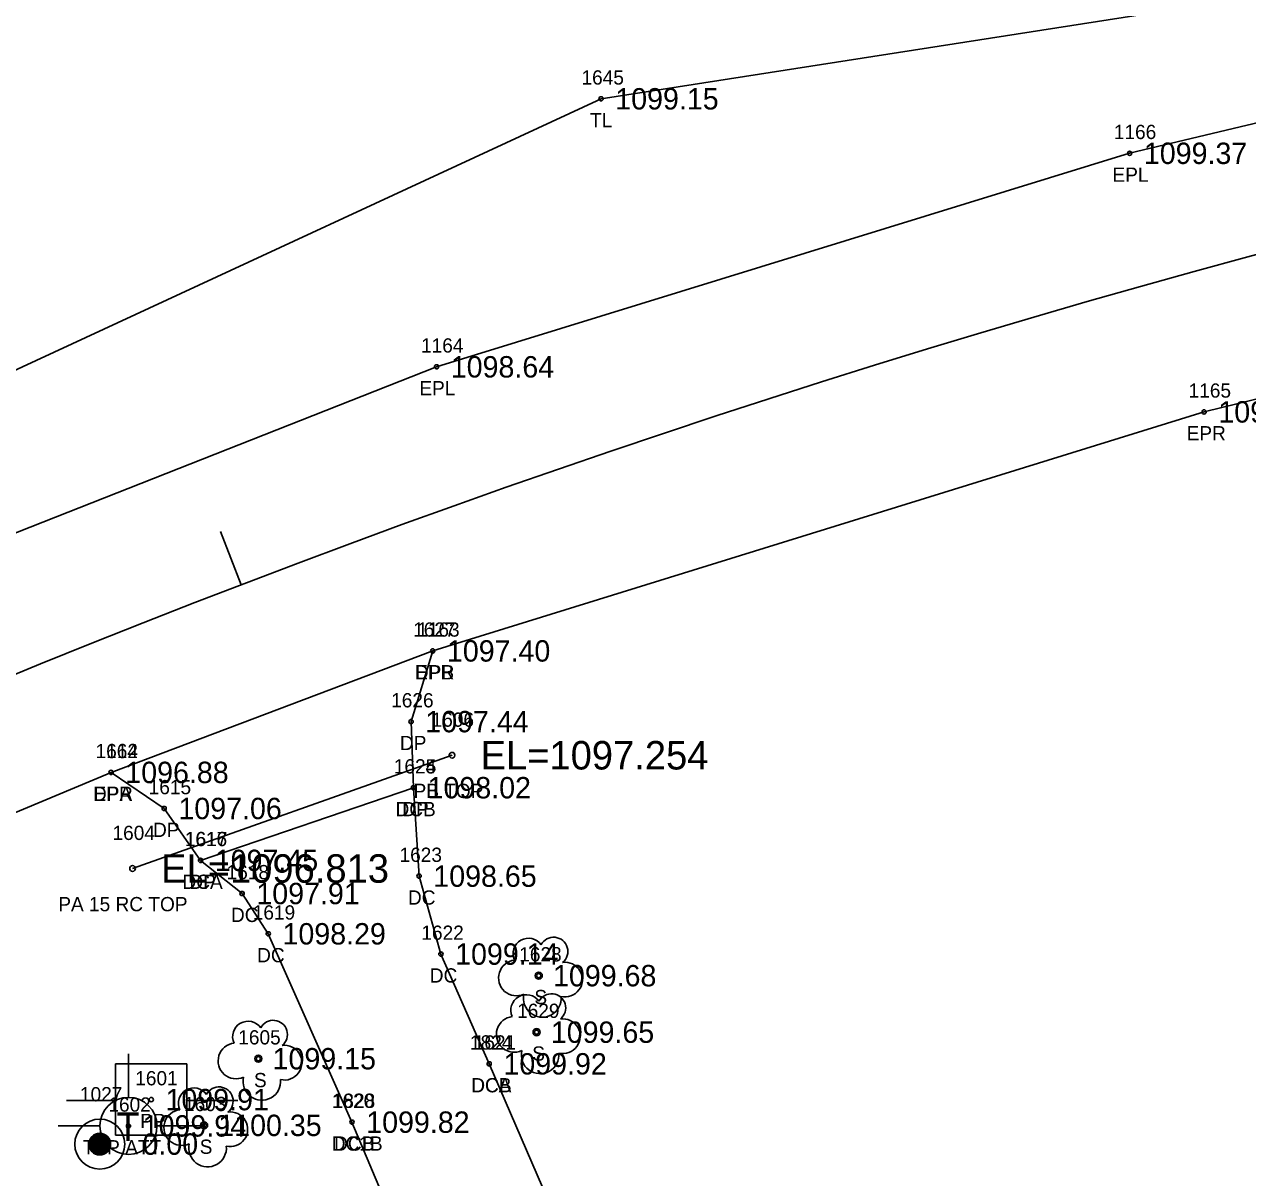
# Model space of a CAD drawing. Extents: x 1539151 to 1541799, y 1198646 to 1201165.
# Drawn here: x 1541070.5 to 1541156.3, y 1200343.1 to 1200424.1 of the extents above; entities that cross this region are included whole.
import ezdxf

# ---------------------------------------------------------------- set-up
doc = ezdxf.new("R2010")
doc.units = 0
for name, color, linetype in [('RD_EX_Conc', 7, 'Continuous'), ('RD_EX_Conc_txCode', 7, 'Continuous'), ('RD_EX_DR_Pipe', 7, 'Continuous'), ('RD_EX_DR_Pipe_txCode', 7, 'Continuous'), ('RD_EX_Driveway', 7, 'Continuous'), ('RD_EX_Driveway_txCode', 7, 'Continuous'), ('RD_EX_DV_Prop_txCode', 7, 'Continuous'), ('RD_EX_DV_PropPin', 7, 'Continuous'), ('RD_EX_Road', 7, 'Continuous'), ('RD_EX_Road_txCode', 7, 'Continuous'), ('RD_EX_TX_Conc_ELEV', 7, 'Continuous'), ('RD_EX_TX_Driveway_ELEV', 7, 'Continuous'), ('RD_EX_TX_DV_Prop_ELEV', 7, 'Continuous'), ('RD_EX_TX_Road_ELEV', 7, 'Continuous'), ('RD_EX_TX_UT_ELEV', 7, 'Continuous'), ('RD_EX_TX_VEG_ELEV', 7, 'Continuous'), ('RD_EX_UT', 7, 'Continuous'), ('RD_EX_UT_txCode', 7, 'Continuous'), ('RD_EX_VEG', 7, 'Continuous'), ('RD_EX_VEG_txCode', 7, 'Continuous'), ('RD_HC_Cl', 7, 'Continuous'), ('RD_HC_Data_Tic', 7, 'Continuous'), ('RD_HC_Survey_ELEV', 7, 'Continuous'), ('RD_SMD_Locator', 7, 'Continuous'), ('RD_TX_Pipe_ElevEX', 7, 'Continuous')]:
    doc.layers.add(name, color=color, linetype=linetype)

msp = doc.modelspace()

# ---------------------------------------------------------------- linework, layer by layer
at = {"layer": 'RD_EX_Conc'}
for points in [[(1541103.059, 1200351.109), (1541099.671, 1200358.812), (1541098.14, 1200364.281), (1541097.739, 1200370.487)], [(1541082.811, 1200365.386), (1541085.726, 1200363.062), (1541087.561, 1200360.234), (1541093.435, 1200347.016)], [(1541126.431, 1200299.676), (1541117.278, 1200318.219), (1541103.059, 1200351.109)], [(1541121.467, 1200290.074), (1541107.496, 1200313.64), (1541093.435, 1200347.016)]]:
    msp.add_lwpolyline(points, dxfattribs=at)
at = {"layer": 'RD_EX_DR_Pipe'}
msp.add_line((1541078.044, 1200364.817), (1541100.453, 1200372.765), dxfattribs=at)
at = {"layer": 'RD_EX_Driveway'}
msp.add_lwpolyline([(1541076.533, 1200371.562), (1541080.259, 1200369.029), (1541082.811, 1200365.386), (1541097.739, 1200370.487), (1541097.578, 1200375.125), (1541099.096, 1200380.088)], dxfattribs=at)
at = {"layer": 'RD_EX_DV_PropPin'}
for p, q in [((1541075.634, 1200344.723), (1541075.634, 1200346.23)), ((1541075.669, 1200344.719), (1541075.669, 1200346.234)), ((1541075.704, 1200344.716), (1541075.704, 1200346.237)), ((1541075.739, 1200344.715), (1541075.739, 1200346.237)), ((1541075.774, 1200344.716), (1541075.774, 1200346.237)), ((1541075.809, 1200344.719), (1541075.809, 1200346.234)), ((1541075.844, 1200344.723), (1541075.844, 1200346.23)), ((1541075.003, 1200345.28), (1541075.003, 1200345.673)), ((1541075.038, 1200345.178), (1541075.038, 1200345.774)), ((1541075.074, 1200345.107), (1541075.074, 1200345.846)), ((1541075.109, 1200345.05), (1541075.109, 1200345.903)), ((1541075.144, 1200345.002), (1541075.144, 1200345.951)), ((1541075.179, 1200344.961), (1541075.179, 1200345.991)), ((1541075.214, 1200344.926), (1541075.214, 1200346.027)), ((1541075.249, 1200344.894), (1541075.249, 1200346.059)), ((1541075.284, 1200344.867), (1541075.284, 1200346.086)), ((1541075.319, 1200344.842), (1541075.319, 1200346.111)), ((1541075.354, 1200344.82), (1541075.354, 1200346.133)), ((1541075.389, 1200344.801), (1541075.389, 1200346.152)), ((1541075.424, 1200344.784), (1541075.424, 1200346.169)), ((1541075.459, 1200344.769), (1541075.459, 1200346.184)), ((1541075.494, 1200344.756), (1541075.494, 1200346.197)), ((1541075.529, 1200344.745), (1541075.529, 1200346.208)), ((1541075.564, 1200344.736), (1541075.564, 1200346.217)), ((1541075.599, 1200344.728), (1541075.599, 1200346.224)), ((1541075.879, 1200344.728), (1541075.879, 1200346.224)), ((1541075.914, 1200344.736), (1541075.914, 1200346.217)), ((1541075.949, 1200344.745), (1541075.949, 1200346.208)), ((1541075.984, 1200344.756), (1541075.984, 1200346.197)), ((1541076.019, 1200344.769), (1541076.019, 1200346.184)), ((1541076.054, 1200344.784), (1541076.054, 1200346.169)), ((1541076.089, 1200344.801), (1541076.089, 1200346.152)), ((1541076.124, 1200344.82), (1541076.124, 1200346.133)), ((1541076.159, 1200344.842), (1541076.159, 1200346.111)), ((1541076.194, 1200344.867), (1541076.194, 1200346.086)), ((1541076.229, 1200344.894), (1541076.229, 1200346.059)), ((1541076.264, 1200344.926), (1541076.264, 1200346.027)), ((1541076.299, 1200344.961), (1541076.299, 1200345.991)), ((1541076.334, 1200345.002), (1541076.334, 1200345.951)), ((1541076.369, 1200345.05), (1541076.369, 1200345.903)), ((1541076.404, 1200345.107), (1541076.404, 1200345.846)), ((1541076.439, 1200345.178), (1541076.439, 1200345.774)), ((1541076.474, 1200345.28), (1541076.474, 1200345.673))]:
    msp.add_line(p, q, dxfattribs=at)
for radius in [1.75, 0.761]:
    msp.add_circle((1541075.739, 1200345.476), radius, dxfattribs=at)
at = {"layer": 'RD_EX_Road'}
for points in [[(1540705.322, 1200094.038), (1540739.01, 1200131.561), (1540770.497, 1200167.373), (1540805.537, 1200205.845), (1540841.216, 1200241.631), (1540879.368, 1200275.734), (1540919.786, 1200306.259), (1540962.727, 1200334.431), (1541008.04, 1200359.974), (1541051.863, 1200381.288), (1541099.365, 1200400.025), (1541147.987, 1200415.009), (1541197.225, 1200426.761), (1541247.293, 1200435.809)], [(1540718.68, 1200081.327), (1540762.243, 1200130.195), (1540779.722, 1200149.92), (1540818.991, 1200193.085), (1540844.694, 1200219.089), (1540861.587, 1200235.219), (1540891.57, 1200261.374), (1540930.279, 1200290.778), (1540971.824, 1200318.199), (1541015.093, 1200342.794), (1541060.357, 1200364.795), (1541076.533, 1200371.562), (1541099.096, 1200380.088), (1541153.211, 1200396.862), (1541201.214, 1200408.644), (1541249.91, 1200417.319)]]:
    msp.add_lwpolyline(points, dxfattribs=at)
at = {"layer": 'RD_EX_UT'}
for p, q in [((1541077.756, 1200351.821), (1541077.756, 1200348.752)), ((1541081.847, 1200351.108), (1541076.847, 1200351.108)), ((1541076.847, 1200351.108), (1541076.847, 1200346.108)), ((1541081.847, 1200346.108), (1541081.847, 1200351.108)), ((1541073.416, 1200348.546), (1541076.885, 1200348.546)), ((1541081.775, 1200348.546), (1541085.416, 1200348.546)), ((1541072.825, 1200346.767), (1541075.756, 1200346.767)), ((1541079.756, 1200346.767), (1541082.825, 1200346.767)), ((1541076.847, 1200346.108), (1541081.847, 1200346.108))]:
    msp.add_line(p, q, dxfattribs=at)
msp.add_circle((1541077.756, 1200346.752), 2, dxfattribs=at)
at = {"layer": 'RD_EX_VEG'}
msp.add_lwpolyline([(1541184.888, 1200430.38), (1541110.905, 1200418.834), (1540957.415, 1200347.719), (1540870.985, 1200282.613), (1540802.214, 1200226.224), (1540781.044, 1200235.771)], dxfattribs=at)
for centre in [(1541106.537, 1200357.296), (1541106.385, 1200353.331), (1541086.866, 1200351.468), (1541083.058, 1200346.791)]:
    msp.add_circle(centre, 0.25, dxfattribs=at)
for centre, radius, start, end in [((1541107.582, 1200358.998), 0.995, 308.76261, 152.04674), ((1541105.816, 1200358.843), 1.084, 34.97629, 204.75602), ((1541104.973, 1200357.14), 1.257, 96.45179, 294.73401), ((1541108.377, 1200357.016), 1.218, 256.56668, 98.10463), ((1541105.664, 1200354.878), 1.084, 34.97629, 204.75602), ((1541106.783, 1200355.699), 1.318, 166.88266, 5.75893), ((1541107.431, 1200355.033), 0.995, 308.76261, 152.04674), ((1541086.145, 1200353.015), 1.084, 34.97629, 204.75602), ((1541087.911, 1200353.17), 0.995, 308.76261, 152.04674), ((1541104.822, 1200353.175), 1.257, 96.45179, 294.73401), ((1541108.225, 1200353.051), 1.218, 256.56668, 98.10463), ((1541085.302, 1200351.313), 1.257, 96.45179, 294.73401), ((1541088.706, 1200351.189), 1.218, 256.56668, 98.10463), ((1541106.631, 1200351.734), 1.318, 166.88266, 5.75893), ((1541087.112, 1200349.872), 1.318, 166.88266, 5.75893), ((1541082.337, 1200348.338), 1.084, 34.97629, 204.75602), ((1541084.104, 1200348.493), 0.995, 308.76261, 152.04674), ((1541081.495, 1200346.636), 1.257, 96.45179, 294.73401), ((1541084.898, 1200346.512), 1.218, 256.56668, 98.10463), ((1541083.304, 1200345.195), 1.318, 166.88266, 5.75893)]:
    msp.add_arc(centre, radius, start, end, dxfattribs=at)
at = {"layer": 'RD_HC_Cl'}
msp.add_arc((1541347.273, 1199701.685), 731.435, 99.312315, 138.327529, dxfattribs=at)
at = {"layer": 'RD_HC_Data_Tic'}
msp.add_line((1541085.653, 1200384.731), (1541084.222, 1200388.466), dxfattribs=at)
at = {"layer": 'RD_SMD_Locator'}
for centre, radius in [((1541110.905, 1200418.834), 0.15), ((1541147.987, 1200415.009), 0.15), ((1541099.365, 1200400.025), 0.15), ((1541153.211, 1200396.862), 0.15), ((1541099.096, 1200380.088), 0.15), ((1541099.096, 1200380.088), 0.15), ((1541097.578, 1200375.125), 0.15), ((1541100.453, 1200372.765), 0.2), ((1541076.533, 1200371.562), 0.15), ((1541076.533, 1200371.562), 0.15), ((1541097.739, 1200370.487), 0.15), ((1541097.739, 1200370.487), 0.15), ((1541080.259, 1200369.029), 0.15), ((1541082.811, 1200365.386), 0.15), ((1541082.811, 1200365.386), 0.15), ((1541078.044, 1200364.817), 0.2), ((1541098.14, 1200364.281), 0.15), ((1541085.726, 1200363.062), 0.15), ((1541087.561, 1200360.234), 0.15), ((1541099.671, 1200358.812), 0.15), ((1541106.537, 1200357.296), 0.15), ((1541106.385, 1200353.331), 0.15), ((1541086.866, 1200351.468), 0.15), ((1541103.059, 1200351.109), 0.15), ((1541103.059, 1200351.109), 0.15), ((1541079.356, 1200348.599), 0.15), ((1541093.435, 1200347.016), 0.15), ((1541093.435, 1200347.016), 0.15), ((1541077.756, 1200346.752), 0.15), ((1541083.058, 1200346.791), 0.15), ((1541075.739, 1200345.476), 0.15)]:
    msp.add_circle(centre, radius, dxfattribs=at)

# ---------------------------------------------------------------- texts
at = {"layer": 'RD_EX_Conc_txCode'}
for s, p in [('1624', (1541096.369, 1200371.487)), ('DCB', (1541096.487, 1200368.487)), ('1617', (1541081.724, 1200366.386)), ('1623', (1541096.77, 1200365.281)), ('DCA', (1541081.543, 1200363.386)), ('1618', (1541084.639, 1200364.062)), ('DC', (1541097.36, 1200362.281)), ('DC', (1541084.946, 1200361.062)), ('1619', (1541086.474, 1200361.234)), ('1622', (1541098.301, 1200359.812)), ('DC', (1541086.781, 1200358.234)), ('DC', (1541098.891, 1200356.812)), ('1824', (1541101.712, 1200352.109)), ('1621', (1541101.972, 1200352.109)), ('DCA', (1541101.791, 1200349.109)), ('DCB', (1541101.807, 1200349.109)), ('1620', (1541092.026, 1200348.016)), ('1828', (1541092.089, 1200348.016)), ('DC1B', (1541092.018, 1200345.016)), ('DCB', (1541092.183, 1200345.016))]:
    msp.add_text(s, height=1, dxfattribs=at).set_placement(p)
at = {"layer": 'RD_EX_DR_Pipe_txCode'}
for s, p in [('1606', (1541099.02, 1200374.765)), ('PB TOP', (1541097.753, 1200369.765)), ('1604', (1541076.635, 1200366.817)), ('PA 15 RC TOP', (1541072.832, 1200361.817))]:
    msp.add_text(s, height=1, dxfattribs=at).set_placement(p)
at = {"layer": 'RD_EX_Driveway_txCode'}
for s, p in [('1627', (1541097.726, 1200381.088)), ('DPB', (1541097.844, 1200378.088)), ('1626', (1541096.184, 1200376.125)), ('DP', (1541096.798, 1200373.125)), ('1614', (1541075.446, 1200372.562)), ('1625', (1541096.369, 1200371.487)), ('DPA', (1541075.265, 1200369.562)), ('1615', (1541079.173, 1200370.029)), ('DP', (1541096.959, 1200368.487)), ('DP', (1541079.48, 1200367.029)), ('1616', (1541081.701, 1200366.386)), ('DP', (1541082.031, 1200363.386))]:
    msp.add_text(s, height=1, dxfattribs=at).set_placement(p)
at = {"layer": 'RD_EX_DV_Prop_txCode'}
msp.add_text('1027', height=1, dxfattribs=at).set_placement((1541074.353, 1200348.476))
at = {"layer": 'RD_EX_Road_txCode'}
for s, p in [('1166', (1541146.877, 1200416.009)), ('EPL', (1541146.782, 1200413.009)), ('1164', (1541098.279, 1200401.025)), ('EPL', (1541098.161, 1200398.025)), ('1165', (1541152.124, 1200397.862)), ('EPR', (1541151.983, 1200394.862)), ('1163', (1541098.009, 1200381.088)), ('EPR', (1541097.867, 1200378.088)), ('1162', (1541075.446, 1200372.562)), ('EPR', (1541075.305, 1200369.562))]:
    msp.add_text(s, height=1, dxfattribs=at).set_placement(p)
at = {"layer": 'RD_EX_TX_Conc_ELEV'}
for s, p in [('1098.02', (1541098.739, 1200369.737)), ('1097.45', (1541083.811, 1200364.636)), ('1098.65', (1541099.14, 1200363.531)), ('1097.91', (1541086.726, 1200362.312)), ('1098.29', (1541088.561, 1200359.484)), ('1099.14', (1541100.671, 1200358.062)), ('1099.92', (1541104.059, 1200350.359)), ('1099.92', (1541104.059, 1200350.359)), ('1099.82', (1541094.435, 1200346.266)), ('1099.82', (1541094.435, 1200346.266))]:
    msp.add_text(s, height=1.5, dxfattribs=at).set_placement(p)
at = {"layer": 'RD_EX_TX_Driveway_ELEV'}
for s, p in [('1097.40', (1541100.096, 1200379.338)), ('1097.44', (1541098.578, 1200374.375)), ('1096.88', (1541077.533, 1200370.812)), ('1098.02', (1541098.739, 1200369.737)), ('1097.06', (1541081.259, 1200368.279)), ('1097.45', (1541083.811, 1200364.636))]:
    msp.add_text(s, height=1.5, dxfattribs=at).set_placement(p)
at = {"layer": 'RD_EX_TX_DV_Prop_ELEV'}
msp.add_text('0.00', height=1.5, dxfattribs=at).set_placement((1541078.739, 1200344.726))
at = {"layer": 'RD_EX_TX_Road_ELEV'}
for s, p in [('1099.37', (1541148.987, 1200414.259)), ('1098.64', (1541100.365, 1200399.275)), ('1098.54', (1541154.211, 1200396.112)), ('1097.40', (1541100.096, 1200379.338)), ('1096.88', (1541077.533, 1200370.812))]:
    msp.add_text(s, height=1.5, dxfattribs=at).set_placement(p)
at = {"layer": 'RD_EX_TX_UT_ELEV'}
msp.add_text('1099.94', height=1.5, dxfattribs=at).set_placement((1541078.756, 1200346.002))
at = {"layer": 'RD_EX_TX_VEG_ELEV'}
for s, p in [('1099.15', (1541111.905, 1200418.084)), ('1099.68', (1541107.537, 1200356.546)), ('1099.65', (1541107.385, 1200352.581)), ('1099.15', (1541087.866, 1200350.718)), ('1100.35', (1541084.058, 1200346.041))]:
    msp.add_text(s, height=1.5, dxfattribs=at).set_placement(p)
at = {"layer": 'RD_EX_UT'}
msp.add_text('T', height=2, dxfattribs=at).set_placement((1541076.907, 1200345.704))
at = {"layer": 'RD_EX_UT_txCode'}
for s, p in [('1601', (1541078.23, 1200349.599)), ('1602', (1541076.346, 1200347.752)), ('PP', (1541078.576, 1200346.599)), ('TPP ATT', (1541074.551, 1200344.752))]:
    msp.add_text(s, height=1, dxfattribs=at).set_placement(p)
at = {"layer": 'RD_EX_VEG_txCode'}
for s, p in [('1645', (1541109.535, 1200419.834)), ('TL', (1541110.134, 1200416.834)), ('1628', (1541105.167, 1200358.296)), ('S', (1541106.23, 1200355.296)), ('1629', (1541105.015, 1200354.331)), ('1605', (1541085.457, 1200352.468)), ('S', (1541106.078, 1200351.331)), ('S', (1541086.559, 1200349.468)), ('1603', (1541081.649, 1200347.791)), ('S', (1541082.751, 1200344.791))]:
    msp.add_text(s, height=1, dxfattribs=at).set_placement(p)
at = {"layer": 'RD_HC_Survey_ELEV'}
msp.add_text('1099.91', height=1.5, dxfattribs=at).set_placement((1541080.356, 1200347.849))
at = {"layer": 'RD_TX_Pipe_ElevEX'}
for s, p in [('EL=1097.254', (1541102.453, 1200371.765)), ('EL=1096.813', (1541080.044, 1200363.817))]:
    msp.add_text(s, height=2, dxfattribs=at).set_placement(p)

doc.saveas('drawing.dxf')
